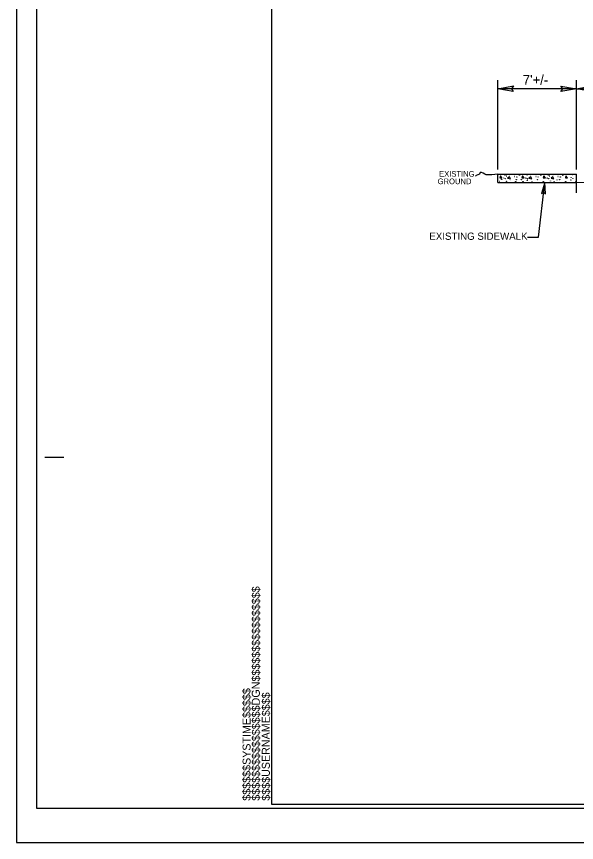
# Model space of a CAD drawing. Extents: x 1022283 to 1026986, y 174822 to 180471.
# Drawn here: x 1022283 to 1023200, y 174822 to 176176 of the extents above; entities that cross this region are included whole.
import ezdxf

# ---------------------------------------------------------------- set-up
doc = ezdxf.new("R2010")
doc.units = 0
for name, color, linetype in [('Default', 7, 'Continuous'), ('Prop Dimension', 7, 'Continuous'), ('Prop Terminator CELL', 7, 'Continuous'), ('Sheet Cutting Line CELL', 7, 'Continuous'), ('Sheet Plot Border Inside CELL', 7, 'Continuous'), ('Sheet Plot Border Outside CELL', 7, 'Continuous'), ('Sheet Typical CELL', 7, 'Continuous'), ('Typical Curb CELL', 7, 'Continuous'), ('Typical Slope Point Local CELL', 7, 'Continuous'), ('Typical Text General CELL', 7, 'Continuous')]:
    doc.layers.add(name, color=color, linetype=linetype)

# ---------------------------------------------------------------- blocks, each defined once
blk = doc.blocks.new('Terminator')
at = {"layer": 'Prop Terminator CELL'}
blk.add_lwpolyline([(-9, 1.55), (0, 0), (-9.05, -1.6), (-7.9, 0)], close=True, dxfattribs=at)

msp = doc.modelspace()

# ---------------------------------------------------------------- linework, layer by layer
at = {"layer": 'Default'}
for p, q in [((1023071.4, 175925.5), (1023071.4, 176071.8)), ((1023071.4, 175925.5), (1023071.4, 176071.8)), ((1023200.2, 175925.5), (1023200.2, 176071.8)), ((1023200.2, 176057.8), (1023071.4, 176057.8)), ((1023200.2, 176057.8), (1023331.7, 176057.8))]:
    msp.add_line(p, q, dxfattribs=at)
at = {"layer": 'Prop Dimension'}
for p, q in [((1023200.2, 175904.2), (1023830.5, 175916.8)), ((1023138.1, 175814.5), (1023148.4, 175904.2)), ((1023119.9, 175814.5), (1023138.1, 175814.5))]:
    msp.add_line(p, q, dxfattribs=at)
at = {"layer": 'Prop Terminator CELL'}
for points in [[(1023096.7, 176053.4), (1023071.4, 176057.8), (1023096.8, 176062.3), (1023093.6, 176057.8)], [(1023174.8, 176062.1), (1023200.2, 176057.8), (1023174.7, 176053.3), (1023177.9, 176057.8)], [(1023225.5, 176053.4), (1023200.2, 176057.8), (1023225.6, 176062.3), (1023222.4, 176057.8)]]:
    msp.add_lwpolyline(points, close=True, dxfattribs=at)
at = {"layer": 'Sheet Cutting Line CELL'}
for p, q in [((1022283.2, 177572.5), (1022283.2, 174822.5)), ((1022283.2, 174822.5), (1026493.2, 174822.5))]:
    msp.add_line(p, q, dxfattribs=at)
at = {"layer": 'Sheet Plot Border Inside CELL'}
msp.add_lwpolyline([(1026482, 177516.3), (1022315.7, 177516.3), (1022315.7, 174878.6), (1026482, 174878.6)], close=True, dxfattribs=at)
at = {"layer": 'Sheet Plot Border Outside CELL'}
msp.add_lwpolyline([(1026493.2, 177572.5), (1022283.2, 177572.5), (1022283.2, 174822.5), (1026493.2, 174822.5)], close=True, dxfattribs=at)
at = {"layer": 'Sheet Typical CELL'}
for p, q in [((1022329.5, 175453.7), (1022360.7, 175453.7)), ((1022700.7, 174885), (1022700.7, 174885)), ((1022700.7, 174885), (1022700.7, 174885)), ((1022700.7, 174885), (1022700.7, 174885)), ((1022700.7, 174885), (1022700.7, 174885)), ((1022700.7, 174885), (1022700.7, 174885)), ((1022700.7, 174885), (1022700.7, 174885))]:
    msp.add_line(p, q, dxfattribs=at)
msp.add_lwpolyline([(1026450.7, 177510), (1022700.7, 177510), (1022700.7, 174885), (1026450.7, 174885)], close=True, dxfattribs=at)
msp.add_lwpolyline([(1022794.5, 174885), (1022794.5, 174885)], dxfattribs=at)
at = {"layer": 'Typical Curb CELL'}
for p, q in [((1023071.4, 175917.8), (1023200.2, 175917.8)), ((1023071.4, 175904.2), (1023071.4, 175917.8)), ((1023200.2, 175908.1), (1023200.2, 175917.8)), ((1023200.2, 175887.2), (1023200.2, 175917.8)), ((1023200.2, 175908.1), (1023200.2, 175917.8)), ((1023071.4, 175904.2), (1023200.2, 175904.2)), ((1023075.6, 175915.1), (1023074.6, 175911.8)), ((1023074.6, 175911.8), (1023078.1, 175911.6)), ((1023078.1, 175911.6), (1023075.6, 175915.1)), ((1023090.3, 175913.4), (1023087.3, 175911.3)), ((1023087.3, 175911.3), (1023092.2, 175910.1)), ((1023092.2, 175910.1), (1023090.3, 175913.4)), ((1023111.9, 175915.1), (1023110.9, 175911.8)), ((1023110.9, 175911.8), (1023114.4, 175911.6)), ((1023114.4, 175911.6), (1023111.9, 175915.1)), ((1023125.2, 175913.4), (1023122.2, 175911.3)), ((1023122.2, 175911.3), (1023127, 175910.1)), ((1023127, 175910.1), (1023125.2, 175913.4)), ((1023146.7, 175915.1), (1023145.7, 175911.8)), ((1023145.7, 175911.8), (1023149.2, 175911.6)), ((1023149.2, 175911.6), (1023146.7, 175915.1)), ((1023161.5, 175913.4), (1023158.5, 175911.3)), ((1023158.5, 175911.3), (1023163.3, 175910.1)), ((1023163.3, 175910.1), (1023161.5, 175913.4)), ((1023183, 175915.1), (1023182, 175911.8)), ((1023182, 175911.8), (1023185.6, 175911.6)), ((1023185.6, 175911.6), (1023183, 175915.1))]:
    msp.add_line(p, q, dxfattribs=at)
for centre in [(1023077.1, 175917.4), (1023084.7, 175917.2), (1023090.3, 175917.2), (1023113.4, 175917.4), (1023125.2, 175917.2), (1023148.2, 175917.4), (1023155.8, 175917.2), (1023161.5, 175917.2), (1023184.5, 175917.4), (1023193.8, 175916.8), (1023074, 175905.7), (1023077.7, 175909.3), (1023080.7, 175911.6), (1023083.1, 175916.3), (1023083.5, 175910.3), (1023085.2, 175914.4), (1023085.5, 175905.6), (1023092.1, 175907.3), (1023099, 175913.9), (1023100.7, 175905.3), (1023101.6, 175908.6), (1023102.6, 175913.1), (1023106.9, 175915.6), (1023109.9, 175908.8), (1023112.5, 175905.3), (1023117, 175911.6), (1023119.4, 175916.3), (1023119.5, 175907.8), (1023119.8, 175910.3), (1023127.4, 175904.9), (1023133.8, 175913.9), (1023136.4, 175908.6), (1023137.4, 175913.1), (1023141.8, 175915.6), (1023146, 175905.5), (1023151.9, 175911.6), (1023154.2, 175916.3), (1023154.7, 175910.3), (1023156.3, 175914.4), (1023157.6, 175906.7), (1023163.6, 175905.3), (1023168.2, 175908.4), (1023170.1, 175913.9), (1023172.8, 175908.6), (1023173.8, 175913.1), (1023178.1, 175915.6), (1023182.5, 175905.5), (1023191, 175908.3), (1023191.5, 175912.1), (1023194.2, 175910.8), (1023198.9, 175905.6)]:
    msp.add_circle(centre, 0.233, dxfattribs=at)
at = {"layer": 'Typical Slope Point Local CELL'}
msp.add_lwpolyline([(1023071.4, 175917.8), (1023061.3, 175916.5), (1023058.7, 175916.5), (1023055, 175916.5), (1023052.4, 175916.5), (1023049.9, 175917.8), (1023047.4, 175919.1), (1023044.9, 175920.3), (1023042.3, 175920.3), (1023041.1, 175917.8), (1023038.5, 175916.5), (1023036, 175915.3), (1023034.8, 175914.7)], dxfattribs=at)

# ---------------------------------------------------------------- block references
at = {"layer": 'Prop Dimension', "xscale": 2.0767499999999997, "yscale": -2.076749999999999, "rotation": 83.4116733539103}
msp.add_blockref('Terminator', (1023148.4, 175904.2), dxfattribs=at)

# ---------------------------------------------------------------- texts
at = {"layer": 'Prop Dimension'}
msp.add_text("7'+/-", height=16, dxfattribs=at).set_placement((1023112.3, 176064.3))
at = {"layer": 'Sheet Typical CELL'}
for s, p in [('$$$$$$$$$$$$$$$$DGN$$$$$$$$$$$$$$$$', (1022681.6, 174890.9)), ('$$$$$$SYSTIME$$$$$', (1022666.5, 174890.9)), ('$$$$USERNAME$$$$', (1022698, 174890.9))]:
    msp.add_text(s, height=13.125, rotation=90, dxfattribs=at).set_placement(p)
at = {"layer": 'Typical Slope Point Local CELL'}
for s, p in [('EXISTING ', (1022975.2, 175913.5)), ('GROUND', (1022972.8, 175901.3))]:
    msp.add_text(s, height=9.31, dxfattribs=at).set_placement(p)
at = {"layer": 'Typical Text General CELL'}
msp.add_text('EXISTING SIDEWALK', height=11.898, dxfattribs=at).set_placement((1022959.2, 175810.1))

doc.saveas('drawing.dxf')
